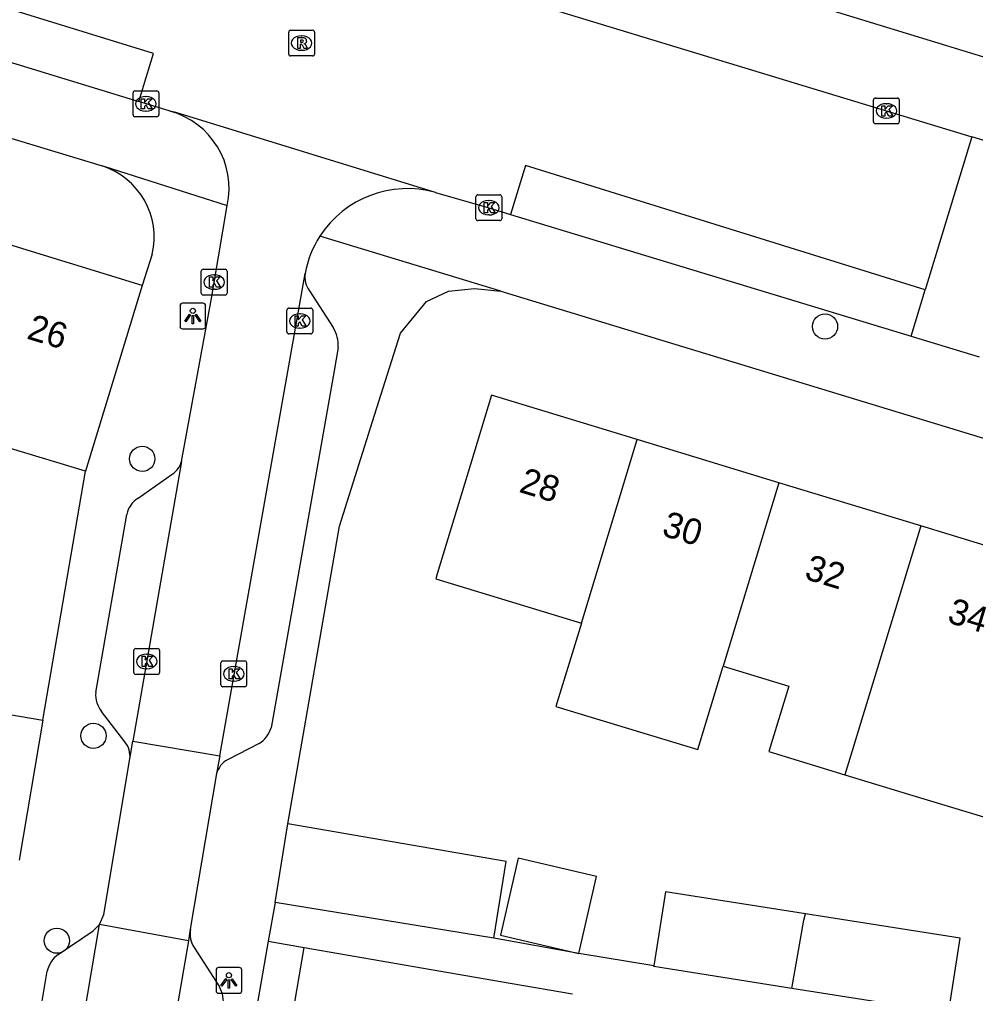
# Model space of a CAD drawing. Extents: x 159822 to 160765, y 380693 to 381634.
# Drawn here: x 160131.44 to 160168.55, y 381030.76 to 381068.56 of the extents above; entities that cross this region are included whole.
import ezdxf

# ---------------------------------------------------------------- set-up
doc = ezdxf.new("R2010")
doc.units = 0
for name, color, linetype in [('IMGEO_Boom', 7, 'Continuous'), ('IMGEO_Kolk', 7, 'Continuous'), ('IMGEO_Lichtpunt', 7, 'Continuous'), ('IMGEO_Muur', 7, 'Continuous'), ('IMGEO_Pand', 7, 'Continuous'), ('IMGEO_Pand_nummerreeks', 7, 'Continuous'), ('IMGEO_Rijbaan_lokaal_open', 7, 'Continuous'), ('IMGEO_Rioolput', 7, 'Continuous'), ('IMGEO_Voetpad_open', 7, 'Continuous')]:
    doc.layers.add(name, color=color, linetype=linetype)

msp = doc.modelspace()

# ---------------------------------------------------------------- linework, layer by layer
at = {"layer": 'IMGEO_Boom'}
for centre in [(160162.708, 381056.645), (160136.208, 381051.508), (160134.315, 381040.761), (160132.895, 381032.809)]:
    msp.add_circle(centre, 0.489, dxfattribs=at)
at = {"layer": 'IMGEO_Kolk'}
for p, q in [((160135.926, 381065.786), (160136.778, 381065.786)), ((160135.851, 381064.86), (160135.851, 381065.712)), ((160136.339, 381065.566), (160136.364, 381065.566)), ((160136.852, 381065.712), (160136.852, 381064.86)), ((160164.589, 381064.586), (160164.589, 381065.438)), ((160164.664, 381065.512), (160165.516, 381065.512)), ((160165.59, 381065.438), (160165.59, 381064.586)), ((160165.077, 381065.292), (160165.102, 381065.292)), ((160136.778, 381064.786), (160135.926, 381064.786)), ((160136.362, 381065.006), (160136.337, 381065.006)), ((160165.1, 381064.732), (160165.075, 381064.732)), ((160165.516, 381064.512), (160164.664, 381064.512)), ((160149.158, 381060.828), (160149.158, 381061.68)), ((160149.233, 381061.754), (160150.085, 381061.754)), ((160150.159, 381061.68), (160150.159, 381060.828)), ((160149.646, 381061.534), (160149.671, 381061.534)), ((160149.669, 381060.974), (160149.644, 381060.974)), ((160150.085, 381060.754), (160149.233, 381060.754)), ((160138.499, 381057.941), (160138.499, 381058.793)), ((160138.574, 381058.867), (160139.426, 381058.867)), ((160138.987, 381058.647), (160139.012, 381058.647)), ((160139.5, 381058.793), (160139.5, 381057.941)), ((160139.426, 381057.867), (160138.574, 381057.867)), ((160139.01, 381058.087), (160138.985, 381058.087)), ((160141.822, 381056.432), (160141.822, 381057.284)), ((160141.897, 381057.358), (160142.749, 381057.358)), ((160142.31, 381057.138), (160142.335, 381057.138)), ((160142.823, 381057.284), (160142.823, 381056.432)), ((160142.749, 381056.358), (160141.897, 381056.358)), ((160142.333, 381056.578), (160142.308, 381056.578)), ((160135.88, 381043.219), (160135.88, 381044.071)), ((160135.955, 381044.145), (160136.807, 381044.145)), ((160136.368, 381043.925), (160136.393, 381043.925)), ((160136.881, 381044.071), (160136.881, 381043.219)), ((160139.26, 381042.739), (160139.26, 381043.591)), ((160139.335, 381043.665), (160140.187, 381043.665)), ((160140.261, 381043.591), (160140.261, 381042.739)), ((160136.807, 381043.145), (160135.955, 381043.145)), ((160136.391, 381043.365), (160136.366, 381043.365)), ((160139.748, 381043.445), (160139.773, 381043.445)), ((160139.771, 381042.885), (160139.746, 381042.885)), ((160140.187, 381042.665), (160139.335, 381042.665))]:
    msp.add_line(p, q, dxfattribs=at)
for points in [[(160135.926, 381065.786), (160136.778, 381065.786)], [(160135.851, 381064.86), (160135.851, 381065.712)], [(160136.172, 381065.486), (160136.295, 381065.486), (160136.295, 381065.335), (160136.425, 381065.486), (160136.589, 381065.486), (160136.443, 381065.335), (160136.596, 381065.086), (160136.444, 381065.086), (160136.359, 381065.25), (160136.295, 381065.183), (160136.295, 381065.086), (160136.172, 381065.086), (160136.172, 381065.486)], [(160136.852, 381065.712), (160136.852, 381064.86)], [(160164.589, 381064.586), (160164.589, 381065.438)], [(160164.664, 381065.512), (160165.516, 381065.512)], [(160165.59, 381065.438), (160165.59, 381064.586)], [(160164.91, 381065.212), (160165.033, 381065.212), (160165.033, 381065.061), (160165.163, 381065.212), (160165.327, 381065.212), (160165.181, 381065.061), (160165.334, 381064.812), (160165.182, 381064.812), (160165.097, 381064.976), (160165.033, 381064.909), (160165.033, 381064.812), (160164.91, 381064.812), (160164.91, 381065.212)], [(160136.778, 381064.786), (160135.926, 381064.786)], [(160165.516, 381064.512), (160164.664, 381064.512)], [(160149.158, 381060.828), (160149.158, 381061.68)], [(160149.233, 381061.754), (160150.085, 381061.754)], [(160150.159, 381061.68), (160150.159, 381060.828)], [(160149.479, 381061.454), (160149.602, 381061.454), (160149.602, 381061.303), (160149.732, 381061.454), (160149.896, 381061.454), (160149.75, 381061.303), (160149.903, 381061.054), (160149.751, 381061.054), (160149.666, 381061.218), (160149.602, 381061.151), (160149.602, 381061.054), (160149.479, 381061.054), (160149.479, 381061.454)], [(160150.085, 381060.754), (160149.233, 381060.754)], [(160138.499, 381057.941), (160138.499, 381058.793)], [(160138.574, 381058.867), (160139.426, 381058.867)], [(160139.5, 381058.793), (160139.5, 381057.941)], [(160138.82, 381058.567), (160138.943, 381058.567), (160138.943, 381058.416), (160139.073, 381058.567), (160139.237, 381058.567), (160139.091, 381058.416), (160139.244, 381058.167), (160139.092, 381058.167), (160139.007, 381058.331), (160138.943, 381058.264), (160138.943, 381058.167), (160138.82, 381058.167), (160138.82, 381058.567)], [(160139.426, 381057.867), (160138.574, 381057.867)], [(160141.822, 381056.432), (160141.822, 381057.284)], [(160141.897, 381057.358), (160142.749, 381057.358)], [(160142.823, 381057.284), (160142.823, 381056.432)], [(160142.143, 381057.058), (160142.266, 381057.058), (160142.266, 381056.907), (160142.396, 381057.058), (160142.56, 381057.058), (160142.414, 381056.907), (160142.567, 381056.658), (160142.415, 381056.658), (160142.33, 381056.822), (160142.266, 381056.755), (160142.266, 381056.658), (160142.143, 381056.658), (160142.143, 381057.058)], [(160142.749, 381056.358), (160141.897, 381056.358)], [(160135.88, 381043.219), (160135.88, 381044.071)], [(160135.955, 381044.145), (160136.807, 381044.145)], [(160136.881, 381044.071), (160136.881, 381043.219)], [(160136.201, 381043.845), (160136.324, 381043.845), (160136.324, 381043.694), (160136.454, 381043.845), (160136.618, 381043.845), (160136.472, 381043.694), (160136.625, 381043.445), (160136.473, 381043.445), (160136.388, 381043.609), (160136.324, 381043.542), (160136.324, 381043.445), (160136.201, 381043.445), (160136.201, 381043.845)], [(160139.26, 381042.739), (160139.26, 381043.591)], [(160139.335, 381043.665), (160140.187, 381043.665)], [(160140.261, 381043.591), (160140.261, 381042.739)], [(160136.807, 381043.145), (160135.955, 381043.145)], [(160139.581, 381043.365), (160139.704, 381043.365), (160139.704, 381043.214), (160139.834, 381043.365), (160139.998, 381043.365), (160139.852, 381043.214), (160140.005, 381042.965), (160139.853, 381042.965), (160139.768, 381043.129), (160139.704, 381043.062), (160139.704, 381042.965), (160139.581, 381042.965), (160139.581, 381043.365)], [(160140.187, 381042.665), (160139.335, 381042.665)]]:
    msp.add_lwpolyline(points, dxfattribs=at)
for centre, start, end in [((160135.928, 381065.71), 91.552, 178.448), ((160135.928, 381065.71), 91.552, 178.448), ((160136.776, 381065.71), 1.552, 88.448), ((160136.776, 381065.71), 1.552, 88.448), ((160164.666, 381065.436), 91.552, 178.448), ((160164.666, 381065.436), 91.552, 178.448), ((160165.514, 381065.436), 1.552, 88.448), ((160165.514, 381065.436), 1.552, 88.448), ((160135.928, 381064.862), 181.552, 268.448), ((160135.928, 381064.862), 181.552, 268.448), ((160136.776, 381064.862), 271.552, 358.448), ((160136.776, 381064.862), 271.552, 358.448), ((160164.666, 381064.588), 181.552, 268.448), ((160164.666, 381064.588), 181.552, 268.448), ((160165.514, 381064.588), 271.552, 358.448), ((160165.514, 381064.588), 271.552, 358.448), ((160149.235, 381061.678), 91.552, 178.448), ((160149.235, 381061.678), 91.552, 178.448), ((160150.083, 381061.678), 1.552, 88.448), ((160150.083, 381061.678), 1.552, 88.448), ((160149.235, 381060.83), 181.552, 268.448), ((160149.235, 381060.83), 181.552, 268.448), ((160150.083, 381060.83), 271.552, 358.448), ((160150.083, 381060.83), 271.552, 358.448), ((160138.576, 381058.791), 91.552, 178.448), ((160138.576, 381058.791), 91.552, 178.448), ((160139.424, 381058.791), 1.552, 88.448), ((160139.424, 381058.791), 1.552, 88.448), ((160138.576, 381057.943), 181.552, 268.448), ((160138.576, 381057.943), 181.552, 268.448), ((160139.424, 381057.943), 271.552, 358.448), ((160139.424, 381057.943), 271.552, 358.448), ((160141.899, 381057.282), 91.552, 178.448), ((160141.899, 381057.282), 91.552, 178.448), ((160142.747, 381057.282), 1.552, 88.448), ((160142.747, 381057.282), 1.552, 88.448), ((160141.899, 381056.434), 181.552, 268.448), ((160141.899, 381056.434), 181.552, 268.448), ((160142.747, 381056.434), 271.552, 358.448), ((160142.747, 381056.434), 271.552, 358.448), ((160135.957, 381044.069), 91.552, 178.448), ((160135.957, 381044.069), 91.552, 178.448), ((160136.805, 381044.069), 1.552, 88.448), ((160136.805, 381044.069), 1.552, 88.448), ((160139.337, 381043.589), 91.552, 178.448), ((160139.337, 381043.589), 91.552, 178.448), ((160140.185, 381043.589), 1.552, 88.448), ((160140.185, 381043.589), 1.552, 88.448), ((160135.957, 381043.221), 181.552, 268.448), ((160135.957, 381043.221), 181.552, 268.448), ((160136.805, 381043.221), 271.552, 358.448), ((160136.805, 381043.221), 271.552, 358.448), ((160139.337, 381042.741), 181.552, 268.448), ((160139.337, 381042.741), 181.552, 268.448), ((160140.185, 381042.741), 271.552, 358.448), ((160140.185, 381042.741), 271.552, 358.448)]:
    msp.add_arc(centre, 0.0765, start, end, dxfattribs=at)
for centre, major_axis, ratio, start_param, end_param in [((160136.338, 381065.286), (-0.387, 0.002), 0.722429, 4.712389, 7.853982), ((160136.363, 381065.286), (-0.39, 0.002), 0.717154, 1.570796, 4.712389), ((160165.076, 381065.012), (-0.387, 0.002), 0.722429, 4.712389, 7.853982), ((160165.101, 381065.012), (-0.39, 0.002), 0.717154, 1.570796, 4.712389), ((160149.645, 381061.254), (-0.387, 0.002), 0.722429, 4.712389, 7.853982), ((160149.67, 381061.254), (-0.39, 0.002), 0.717154, 1.570796, 4.712389), ((160138.986, 381058.367), (-0.387, 0.002), 0.722429, 4.712389, 7.853982), ((160139.011, 381058.367), (-0.39, 0.002), 0.717154, 1.570796, 4.712389), ((160142.309, 381056.858), (-0.387, 0.002), 0.722429, 4.712389, 7.853982), ((160142.334, 381056.858), (-0.39, 0.002), 0.717154, 1.570796, 4.712389), ((160136.367, 381043.645), (-0.387, 0.002), 0.722429, 4.712389, 7.853982), ((160136.392, 381043.645), (-0.39, 0.002), 0.717154, 1.570796, 4.712389), ((160139.747, 381043.165), (-0.387, 0.002), 0.722429, 4.712389, 7.853982), ((160139.772, 381043.165), (-0.39, 0.002), 0.717154, 1.570796, 4.712389)]:
    msp.add_ellipse(centre, major_axis=major_axis, ratio=ratio, start_param=start_param, end_param=end_param, dxfattribs=at)
at = {"layer": 'IMGEO_Lichtpunt'}
for p, q in [((160138.576, 381057.55), (160137.768, 381057.55)), ((160138.576, 381057.55), (160137.768, 381057.55)), ((160137.674, 381057.455), (160137.674, 381056.648)), ((160137.674, 381057.455), (160137.674, 381056.648)), ((160138.67, 381056.648), (160138.67, 381057.455)), ((160138.67, 381056.648), (160138.67, 381057.455)), ((160137.768, 381056.554), (160138.576, 381056.554)), ((160137.768, 381056.554), (160138.576, 381056.554)), ((160139.975, 381031.767), (160139.167, 381031.767)), ((160139.975, 381031.767), (160139.167, 381031.767)), ((160139.073, 381031.672), (160139.073, 381030.865)), ((160139.073, 381031.672), (160139.073, 381030.865)), ((160140.069, 381030.865), (160140.069, 381031.672)), ((160140.069, 381030.865), (160140.069, 381031.672)), ((160139.167, 381030.771), (160139.975, 381030.771)), ((160139.167, 381030.771), (160139.975, 381030.771))]:
    msp.add_line(p, q, dxfattribs=at)
for points in [[(160138.048, 381057.119), (160138.087, 381057.091), (160137.899, 381056.829), (160137.861, 381056.856), (160138.048, 381057.119)], [(160138.26, 381057.091), (160138.298, 381057.118), (160138.485, 381056.856), (160138.446, 381056.828), (160138.26, 381057.091)], [(160138.15, 381057.071), (160138.197, 381057.071), (160138.197, 381056.749), (160138.15, 381056.749), (160138.15, 381057.071)], [(160139.447, 381031.336), (160139.486, 381031.308), (160139.298, 381031.046), (160139.26, 381031.073), (160139.447, 381031.336)], [(160139.549, 381031.288), (160139.596, 381031.288), (160139.596, 381030.966), (160139.549, 381030.966), (160139.549, 381031.288)], [(160139.659, 381031.308), (160139.697, 381031.335), (160139.884, 381031.073), (160139.845, 381031.045), (160139.659, 381031.308)]]:
    msp.add_lwpolyline(points, dxfattribs=at)
for centre in [(160138.173, 381057.253), (160139.572, 381031.47)]:
    msp.add_circle(centre, 0.0994, dxfattribs=at)
for centre, start, end in [((160137.768, 381057.455), 90, 180), ((160137.768, 381057.455), 90, 180), ((160138.576, 381057.455), 0, 90), ((160138.576, 381057.455), 0, 90), ((160137.768, 381056.648), 180, 270), ((160137.768, 381056.648), 180, 270), ((160138.576, 381056.648), 270, 0), ((160138.576, 381056.648), 270, 360), ((160139.167, 381031.672), 90, 180), ((160139.167, 381031.672), 90, 180), ((160139.975, 381031.672), 0, 90), ((160139.975, 381031.672), 0, 90), ((160139.167, 381030.865), 180, 270), ((160139.167, 381030.865), 180, 270), ((160139.975, 381030.865), 270, 0), ((160139.975, 381030.865), 270, 360)]:
    msp.add_arc(centre, 0.0946, start, end, dxfattribs=at)
at = {"layer": 'IMGEO_Muur'}
for points in [[(160141.863, 381037.344), (160143.868, 381048.901), (160145.226, 381053.206)], [(160132.354, 381041.37), (160134.008, 381051.026)]]:
    msp.add_lwpolyline(points, dxfattribs=at)
at = {"layer": 'IMGEO_Pand'}
for points in [[(160136.209, 381058.234), (160130.546, 381059.963)], [(160136.209, 381058.234), (160134.008, 381051.026)], [(160155.42, 381052.254), (160149.767, 381053.975), (160148.948, 381051.284), (160147.659, 381047.051), (160147.599, 381046.855), (160153.251, 381045.134)], [(160134.008, 381051.026), (160131.094, 381051.916), (160130.512, 381050.01), (160127.763, 381050.849), (160128.345, 381052.755)], [(160153.251, 381045.134), (160155.42, 381052.254)], [(160160.92, 381050.579), (160155.42, 381052.254)], [(160160.92, 381050.579), (160158.753, 381043.459)], [(160166.421, 381048.904), (160160.92, 381050.579)], [(160166.421, 381048.904), (160163.482, 381039.25)], [(160171.922, 381047.229), (160166.421, 381048.904)], [(160153.251, 381045.134), (160152.265, 381041.899), (160157.767, 381040.223), (160158.753, 381043.459)], [(160158.753, 381043.459), (160161.301, 381042.683), (160160.529, 381040.149), (160163.482, 381039.25)], [(160124.468, 381037.113), (160125.393, 381042.554), (160132.354, 381041.37)], [(160132.354, 381041.37), (160131.429, 381035.928)], [(160163.482, 381039.25), (160165.99, 381038.486), (160168.983, 381037.575), (160169.755, 381040.11)], [(160141.363, 381034.29), (160141.863, 381037.344)], [(160149.851, 381032.903), (160150.338, 381035.884), (160141.863, 381037.344)], [(160153.147, 381032.314), (160153.842, 381035.304), (160150.802, 381036.011), (160150.107, 381033.021), (160153.147, 381032.314)], [(160161.952, 381033.85), (160156.517, 381034.709), (160156.063, 381031.838)], [(160149.851, 381032.903), (160141.363, 381034.29)], [(160161.421, 381030.959), (160161.88, 381033.611), (160161.952, 381033.85)], [(160167.496, 381029.999), (160167.955, 381032.902), (160161.952, 381033.85)], [(160141.659, 381027.698), (160142.494, 381032.543)], [(160142.494, 381032.543), (160147.422, 381031.694), (160150.482, 381031.166), (160152.91, 381030.747)], [(160161.421, 381030.959), (160156.058, 381031.807), (160156.063, 381031.838)], [(160167.496, 381029.999), (160161.421, 381030.959)]]:
    msp.add_lwpolyline(points, dxfattribs=at)
at = {"layer": 'IMGEO_Rijbaan_lokaal_open'}
for points in [[(160108.334, 381082.266), (160168.403, 381064.004)], [(160136.07, 381065.373), (160136.642, 381067.238), (160106.567, 381076.508)], [(160137.286, 381065), (160136.07, 381065.373)], [(160147.591, 381061.846), (160137.514, 381064.952), (160137.286, 381065)], [(160168.403, 381064.004), (160166.598, 381058.064)], [(160171.044, 381063.201), (160168.403, 381064.004)], [(160166.598, 381058.064), (160151.082, 381062.889), (160150.507, 381060.997)], [(160147.591, 381061.846), (160149.618, 381061.267), (160150.507, 381060.997)], [(160137.729, 381051.409), (160138.885, 381057.663), (160138.998, 381058.348), (160139.511, 381061.344)], [(160139.216, 381039.981), (160142.526, 381058.698)], [(160166.054, 381056.274), (160166.598, 381058.064)], [(160166.054, 381056.274), (160168.695, 381055.471)], [(160137.729, 381051.409), (160135.848, 381040.557)], [(160135.728, 381039.863), (160135.848, 381040.557)], [(160135.848, 381040.557), (160139.216, 381039.981)], [(160134.55, 381033.44), (160134.716, 381033.831), (160135.728, 381039.863)], [(160139.216, 381039.981), (160139.094, 381039.294)], [(160139.094, 381039.294), (160138.075, 381033.251)], [(160122.694, 380964.146), (160128.881, 381000), (160134.55, 381033.44)], [(160137.998, 381032.804), (160134.55, 381033.44)], [(160138.075, 381033.251), (160137.998, 381032.804)], [(160137.998, 381032.804), (160132.353, 381000), (160126.083, 380963.562)]]:
    msp.add_lwpolyline(points, dxfattribs=at)
for centre, radius, start, end in [((160136.477, 381062.003), 3.104, 347.749, 74.8994), ((160146.5, 381057.953), 4.043, 74.3412, 147.1371), ((160146.473, 381057.963), 4.015, 147.0495, 169.4568)]:
    msp.add_arc(centre, radius, start, end, dxfattribs=at)
at = {"layer": 'IMGEO_Rioolput'}
for p, q in [((160141.894, 381067.217), (160141.894, 381068.069)), ((160141.969, 381068.143), (160142.821, 381068.143)), ((160142.895, 381068.069), (160142.895, 381067.217)), ((160142.382, 381067.923), (160142.407, 381067.923)), ((160142.405, 381067.363), (160142.38, 381067.363)), ((160142.821, 381067.143), (160141.969, 381067.143))]:
    msp.add_line(p, q, dxfattribs=at)
for points in [[(160141.894, 381067.217), (160141.894, 381068.069)], [(160141.969, 381068.143), (160142.821, 381068.143)], [(160142.895, 381068.069), (160142.895, 381067.217)], [(160142.483, 381067.841), (160142.231, 381067.843), (160142.231, 381067.443)], [(160142.409, 381067.762), (160142.355, 381067.762), (160142.355, 381067.681)], [(160142.355, 381067.681), (160142.407, 381067.681)], [(160142.231, 381067.443), (160142.355, 381067.443), (160142.355, 381067.605), (160142.366, 381067.605)], [(160142.413, 381067.576), (160142.484, 381067.443), (160142.624, 381067.443), (160142.559, 381067.569)], [(160142.821, 381067.143), (160141.969, 381067.143)]]:
    msp.add_lwpolyline(points, dxfattribs=at)
for centre, radius, start, end in [((160141.971, 381068.067), 0.0765, 91.552, 178.448), ((160141.971, 381068.067), 0.0765, 91.552, 178.448), ((160142.819, 381068.067), 0.0765, 1.552, 88.448), ((160142.819, 381068.067), 0.0765, 1.552, 88.448), ((160142.391, 381067.87), 0.19, 274.7715, 282.9687), ((160142.415, 381067.666), 0.0964, 77.0061, 93.1865), ((160142.429, 381067.723), 0.0378, 276.6634, 79.6772), ((160142.482, 381067.731), 0.109, 350.3612, 89.416), ((160142.48, 381067.731), 0.112, 277.5842, 350.9817), ((160142.365, 381067.552), 0.0533, 26.0293, 88.6989), ((160142.464, 381067.516), 0.108, 29.5134, 73.7905), ((160141.971, 381067.219), 0.0765, 181.552, 268.448), ((160141.971, 381067.219), 0.0765, 181.552, 268.448), ((160142.819, 381067.219), 0.0765, 271.552, 358.448), ((160142.819, 381067.219), 0.0765, 271.552, 358.448)]:
    msp.add_arc(centre, radius, start, end, dxfattribs=at)
for centre, major_axis, ratio, start_param, end_param in [((160142.381, 381067.643), (-0.387, 0.002), 0.722429, 4.712389, 7.853982), ((160142.406, 381067.643), (-0.39, 0.002), 0.717154, 1.570796, 4.712389)]:
    msp.add_ellipse(centre, major_axis=major_axis, ratio=ratio, start_param=start_param, end_param=end_param, dxfattribs=at)
at = {"layer": 'IMGEO_Voetpad_open'}
for points in [[(160091.908, 381075.862), (160100.258, 381073.306), (160134.651, 381062.88)], [(160105.982, 381074.601), (160136.07, 381065.373)], [(160190.068, 381060.613), (160153.769, 381071.728), (160152.489, 381072.123)], [(160134.651, 381062.88), (160134.717, 381062.868), (160139.511, 381061.344)], [(160150.507, 381060.997), (160166.054, 381056.274)], [(160150.121, 381058.011), (160143.104, 381060.147)], [(160136.597, 381059.446), (160136.209, 381058.234)], [(160141.863, 381037.344), (160143.868, 381048.901), (160145.226, 381053.206), (160146.229, 381056.386), (160147.241, 381057.618), (160148.094, 381058.014), (160149.108, 381058.121), (160150.121, 381058.011)], [(160142.703, 381058.027), (160143.615, 381056.603)], [(160150.121, 381058.011), (160192.132, 381045.221), (160193.44, 381044.574)], [(160143.812, 381055.835), (160143.662, 381054.928), (160141.211, 381041.065)], [(160132.354, 381041.37), (160134.008, 381051.026)], [(160136.046, 381049.981), (160137.369, 381050.909)], [(160134.403, 381042.435), (160135.606, 381049.351)], [(160135.535, 381040.527), (160134.632, 381041.701)], [(160140.744, 381040.46), (160139.517, 381039.831)], [(160141.363, 381034.29), (160141.101, 381032.785)], [(160132.947, 381032.269), (160134.298, 381033.192), (160134.55, 381033.44)], [(160153.147, 381032.314), (160149.851, 381032.903)], [(160141.101, 381032.785), (160136.17, 381004.405)], [(160138.223, 381032.543), (160139.201, 381031.014)], [(160141.101, 381032.785), (160142.494, 381032.543)], [(160156.063, 381031.838), (160153.147, 381032.314)], [(160131.685, 381026.662), (160132.524, 381031.623)]]:
    msp.add_lwpolyline(points, dxfattribs=at)
for centre, radius, start, end in [((160133.759, 381060.106), 2.913, 346.8987, 72.1806), ((160143.428, 381058.577), 0.91, 172.3578, 217.1965), ((160142.621, 381055.939), 1.195, 355.013, 33.7605), ((160136.892, 381051.632), 0.866, 303.4197, 345.0725), ((160136.567, 381049.148), 0.983, 122.0502, 168.088), ((160135.425, 381042.351), 1.025, 175.3048, 219.35), ((160140.169, 381041.387), 1.091, 301.8326, 342.8383), ((160134.835, 381039.963), 0.899, 353.5834, 38.831), ((160139.95, 381039.055), 0.889, 119.163, 164.3813), ((160139.113, 381033.098), 1.049, 171.6356, 211.9785), ((160133.555, 381031.41), 1.053, 125.2652, 168.3013), ((160138.365, 381030.48), 0.992, 346.7971, 32.5911)]:
    msp.add_arc(centre, radius, start, end, dxfattribs=at)

# ---------------------------------------------------------------- texts
at = {"layer": 'IMGEO_Pand_nummerreeks'}
for s, rotation, p in [('26', 343.0194, (160131.687, 381056.185)), ('28', 343.0634, (160150.794, 381050.233)), ('30', 343.0656, (160156.333, 381048.547)), ('32', 343.0656, (160161.867, 381046.862)), ('34', 343.0656, (160167.409, 381045.175))]:
    msp.add_text(s, height=1, rotation=rotation, dxfattribs=at).set_placement(p)

doc.saveas('drawing.dxf')
